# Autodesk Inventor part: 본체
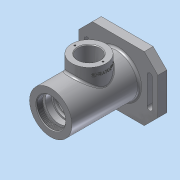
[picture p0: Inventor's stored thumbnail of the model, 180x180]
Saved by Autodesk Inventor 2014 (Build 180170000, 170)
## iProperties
Created: 2017-10
Part Number: 본체
Material: 알루미늄 6061
Document SubType Name: Modeling
Designer: kb542-18
Density: 2.71 g/cm^3
Appearance: 알루미늄 - 평지
Mass: 789.711 g
Surface Area: 662.711 cm^2
Volume: 291.406 cm^3
Author: kb542-18
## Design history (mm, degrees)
sketch "스케치1"
  geometry: C1 r 31 at (0, 0); 1 further point
  constraints: 1 centre point, 1 coincident
  dimensions: "d0" = 62 diameter of C1
extrude "돌출1" new body sketch "스케치1" stored distance "d1" = 99; taper "d2" = 0 deg
sketch "스케치2"
  geometry: L1 (-47, 58)-(47, 58); L2 (47, 58)-(47, -58); L3 (47, -58)-(-47, -58); L4 (-47, -58)-(-47, 58); L5 (-47, 58)-(47, -58); L6 (47, 58)-(-47, -58); C1 r 31 at (0, 0) reference
  constraints: 12 end point, 2 midpoint, 2 parallel, 1 horizontal, 1 perpendicular
  dimensions: "d3" = 116 distance of L3.end L1.start; "d4" = 94 distance of L2.end L3.end
extrude "돌출2" join sketch "스케치2" distance "d5" = 13; taper "d6" = 0 deg
sketch "스케치3"
  geometry: C1 r 35 at (0, 0); 1 further point
  constraints: 1 centre point, 1 coincident
  dimensions: "d7" = 70 diameter of C1
extrude "돌출3" join sketch "스케치3" distance "d8" = 3; taper "d9" = 0 deg
chamfer "모따기1" distance "d10" = 20; stored, may be unused: second distance "d11" = 2, angle "d12" = 45 deg
sketch "스케치4"
  geometry: L1 (-47, 38)-(-47, -38) reference; L2 (-20, -46)-(20, -46); L3 (-20, -42)-(20, -42); L4 (20, -50)-(-20, -50); C1 r 31 at (0, 0) reference; A1 r 4 centre (-20, -46) between (-20, -42) and (-20, -50); A2 r 4 centre (20, -46) between (20, -50) and (20, -42); 1 further point
  constraints: 8 end point, 4 point on circle, 4 tangent, 2 centre point, 1 midpoint, 1 parallel, 1 perpendicular, 1 vertical alignment
  dimensions: "d13" = 46 distance of C1.centre point (0, -46); "d14" = 4 radius of A2; "d15" = 40 distance of L2.end L2.start
extrude "돌출4" cut sketch "스케치4" stored distance "d16" = 3; taper "d17" = 0 deg
sketch "스케치5"
  geometry: L1 (-49.5, 31)-(-49.5, -31) reference; L2 (-49.5, 0)-(-40.5, 0); L3 (-40.5, 0)-(-40.5, 21); L4 (-40.5, 21)-(-49.5, 21); L5 (-49.5, 21)-(-49.5, 0); L6 (-40.5, 0)-(-37.5, 0); L7 (-37.5, 0)-(-37.5, 24); L8 (-37.5, 24)-(-40.5, 24); L9 (-40.5, 24)-(-40.5, 0); L10 (-37.5, 0)-(-28.5, 0); L11 (-28.5, 0)-(-28.5, 20); L12 (-28.5, 20)-(-37.5, 20); L13 (-37.5, 20)-(-37.5, 0); L14 (-28.5, 0)-(-25.25, 0); L15 (-25.25, 0)-(-25.25, 17.5); L16 (-25.25, 17.5)-(-28.5, 17.5); L17 (-28.5, 17.5)-(-28.5, 0); L18 (-25.25, 0)-(-23.5, 0); L19 (-23.5, 0)-(-23.5, 18.5); L20 (-23.5, 18.5)-(-25.25, 18.5); L21 (-25.25, 18.5)-(-25.25, 0); L22 (-23.5, 0)-(-12.5, 0); L23 (-12.5, 0)-(-12.5, 17.5); L24 (-12.5, 17.5)-(-23.5, 17.5); L25 (-23.5, 17.5)-(-23.5, 0); L26 (-12.5, 0)-(25.5, 0); L27 (25.5, 0)-(25.5, 26); L28 (25.5, 26)-(-12.5, 26); L29 (-12.5, 26)-(-12.5, 0); L30 (25.5, 0)-(36.5, 0); L31 (36.5, 0)-(36.5, 17.5); L32 (36.5, 17.5)-(25.5, 17.5); L33 (25.5, 17.5)-(25.5, 0); L34 (36.5, 0)-(41.5, 0); L35 (41.5, 0)-(41.5, 16.5); L36 (41.5, 16.5)-(36.5, 16.5); L37 (36.5, 16.5)-(36.5, 0); L38 (41.5, 0)-(41.5, 0); L39 (41.5, 0)-(41.5, 10); L40 (41.5, 12.858)-(41.5, 0); L41 (41.5, 0)-(44.2, 0); L42 (44.2, 0)-(44.2, 10); L43 (44.2, 10)-(41.5, 10); L44 (41.5, 10)-(41.5, 0); L45 (44.2, 0)-(51.5, 0); L46 (51.5, 0)-(51.5, 12.5); L47 (51.5, 12.5)-(44.2, 12.5); L48 (44.2, 12.5)-(44.2, 0); L49 (65.5, -35)-(65.5, 35) reference; L50 (65.5, 22)-(51.5, 16); L51 (51.5, 16)-(51.5, 0); L52 (51.5, 0)-(65.5, 0); L53 (65.5, 0)-(65.5, 22); 1 further point
  constraints: 102 end point, 23 parallel, 14 perpendicular, 12 horizontal, 3 collinear, 1 midpoint
  dimensions: "d18" = 3 distance of L7.end L8.end; "d20" = 21 distance between parallel lines of L17 L1; "d21" = 12 distance between parallel lines of L13 L1; "d23" = 14 distance between parallel lines of L49 L51; "d24" = 38 distance between parallel lines of L33 L29; "d25" = 11 distance of L23.end L24.end; "d26" = 1.75 distance of L19.end L20.end; "d27" = 11 distance of L31.end L32.end; "d32" = 7.3 distance of L46.end L47.end; "d33" = 2.7 distance of L39.end L42.end; "d34" = 42 diameter of L4 L2; "d35" = 48 diameter of L8 L6; "d36" = 40 diameter of L12 L10; "d37" = 35 diameter of L16 L14; "d38" = 37 diameter of L20 L18; "d39" = 35 diameter of L24 L22; "d40" = 52 diameter of L28 L26; "d41" = 35 diameter of L32 L30; "d42" = 33 diameter of L36 L34; "d43" = 20 diameter of L43 L41; "d44" = 25 diameter of L47 L45; "d47" = 22 distance of L52.end L50.start; "d48" = 32 diameter of L50.end L52; "d49" = 26 distance between parallel lines of L19 L1
revolve "회전1" sketch "스케치5" stored, may be unused: angle "d50" = 90 deg
node "작업 평면1"
sketch "스케치6"
  geometry: L1 (49.5, -31)-(49.5, 31) reference; C1 r 25 at (-6.5, 0); 1 further point
  constraints: 1 centre point, 1 horizontal alignment
  dimensions: "d52" = 50 diameter of C1; "d53" = 56 distance from line of L1 C1.centre
extrude "돌출5" join sketch "스케치6" stored distance "d54" = 3; taper "d55" = 0 deg
sketch "스케치7"
  geometry: C1 r 25 at (0, 0) reference; C2 r 16 at (0, 0); 1 further point
  constraints: 1 centre point, 1 coincident
  dimensions: "d56" = 32 diameter of C2
extrude "돌출6" cut sketch "스케치7" stored distance "d57" = 3; taper "d58" = 0 deg
fillet "모깎기1" dims "d59" = 0.3
chamfer "모따기2" distance "d60" = 0.7; stored, may be unused: second distance "d61" = 2, angle "d62" = 30 deg
fillet "모깎기2" dims "d63" = 3
chamfer "모따기3" distance "d64" = 1; stored, may be unused: second distance "d65" = 2, angle "d66" = 33 deg
node "작업 평면2"
sketch "스케치8"
  geometry: L1 (-31.5, -47)-(18.5, -47) reference; L2 (49.5, -31)-(49.5, 31) reference; 2 further points
  constraints: 1 other
  dimensions: "d67" = 10 distance from line of L1 point (-6.5, -37); "d69" = 56 distance from line of point (-6.5, -37) L2
feature "엠보싱1" sketch "스케치8" dims "d1" = 99, "d2" = 0, "d70" = 0.5, "d71" = 0
sketch "스케치9"
  geometry: L1 (0, 0)-(0, 20.5); L2 (0, 0)-(0, -20.5); C1 r 17 at (0, 0) reference; A1 r 20.5 centre (0, 0) between (0, 20.5) and (0, -20.5); 3 further points
  constraints: 4 end point, 3 coincident, 2 point on circle, 1 centre point, 1 collinear, 1 vertical
  dimensions: "d74" = 41 diameter of A1
hole "구멍1" sketch "스케치9" at (0, 20.5), (0, -20.5) diameter "d75" = 2.459; stored, may be unused: countersink angle "d79" = 90 deg, drill point angle "d81" = 118 deg; dims "d76" = 6, "d77" = 4, "d78" = 2, "d80" = 8
fillet "모깎기3" dims "d82" = 3
chamfer "모따기4" distance "d83" = 1; stored, may be unused: second distance "d84" = 2, angle "d85" = 45 deg
chamfer "모따기5" distance "d86" = 1; stored, may be unused: second distance "d87" = 2, angle "d88" = 45 deg
feature "스레드2" dims "d89" = 10, "d90" = 0
node "솔리드1"
mirror "대칭1"
other parameters: "d51" = -47
